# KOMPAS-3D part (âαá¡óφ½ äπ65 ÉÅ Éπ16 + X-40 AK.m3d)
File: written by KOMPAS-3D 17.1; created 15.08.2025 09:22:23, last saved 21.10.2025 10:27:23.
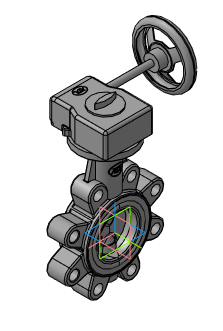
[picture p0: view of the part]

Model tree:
1. Операция без истории:2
